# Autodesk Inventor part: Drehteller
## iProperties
Shininess: 64.0
Length Units: 11269
Angle Units: 11279
Time Units: 11290
Mass Units: 11283
Length Display Precision: 3
Angle Display Precision: 2
Compacted: True
Part Number: Drehteller
Document SubType Name: Modeling
Created: 2004-01
Material: Standard
Designer: chefe
Manufacturer: Standard
Standards Organization: Custom
Density: 0.0
Volumn: 0.0
Area: 0.0
PropertySet Name: Model Information
Control State: 0
Master: False
Checked Out: False
Author: chefe
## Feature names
1. Extrusion1
2. Extrusion2
